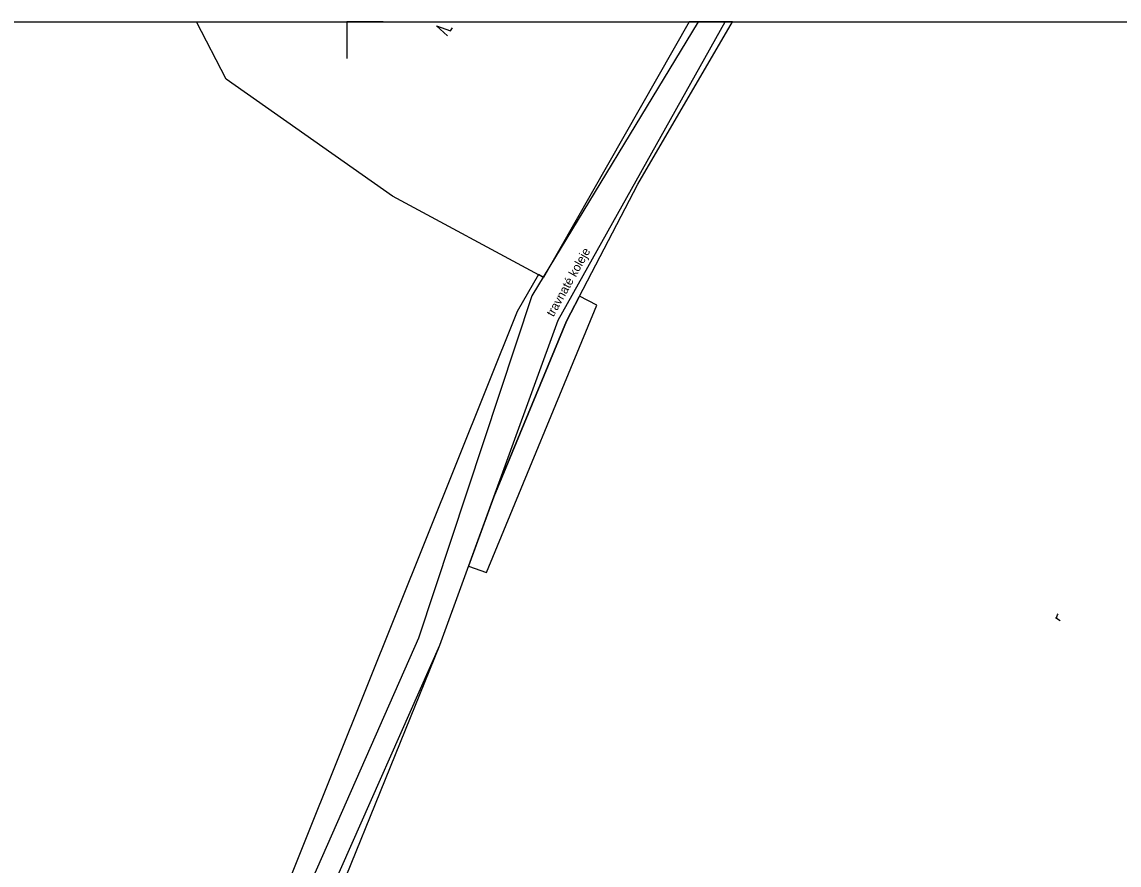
# Model space of a CAD drawing. Extents: x -636600 to -628587, y -1090963 to -1085869.
# Drawn here: x -629681.7 to -629531.6, y -1090043.3 to -1089927.9 of the extents above; entities that cross this region are included whole.
import ezdxf

# ---------------------------------------------------------------- set-up
doc = ezdxf.new("R2010")
doc.units = 0
for name, color, linetype in [('01_PARCELY_NÁVRH_PC', 7, 'Continuous'), ('08_LEGENDA_HV', 7, 'Continuous'), ('15', 7, 'Continuous'), ('40', 7, 'Continuous'), ('42', 7, 'Continuous'), ('43', 7, 'Continuous')]:
    doc.layers.add(name, color=color, linetype=linetype)

msp = doc.modelspace()

# ---------------------------------------------------------------- linework, layer by layer
at = {"layer": '01_PARCELY_NÁVRH_PC'}
msp.add_line((-629584.51, -1089927.9), (-629590.44, -1089927.9), dxfattribs=at)
for points in [[(-629590.44, -1089927.9), (-629610.34, -1089962.86), (-629611.05, -1089962.47), (-629613.94, -1089967.55), (-629651.31, -1090060.76), (-629656.7, -1090071.62), (-629663.92, -1090084.26), (-629669.51, -1090092.1), (-629671.7, -1090096.43), (-629679.1, -1090105.56), (-629740.1, -1090168.89), (-629745.82, -1090175.94), (-629753.08, -1090187.33), (-629759.69, -1090209.29), (-629763.83, -1090224.9)], [(-629757.08, -1090224.9), (-629756.4, -1090222.95), (-629754.36, -1090212.07), (-629743.98, -1090191.89), (-629738.43, -1090182.38), (-629727.31, -1090166.03), (-629671.82, -1090106.56), (-629662.5, -1090094.94), (-629652.06, -1090078.29), (-629645.47, -1090064.84), (-629624.55, -1090013.22), (-629617.14, -1089992.88), (-629607.22, -1089968.87), (-629597.44, -1089950.1), (-629584.51, -1089927.9)]]:
    msp.add_lwpolyline(points, dxfattribs=at)
msp.add_lwpolyline([(-629620.6, -1090002.37), (-629618.16, -1090003.26), (-629603.06, -1089966.65), (-629605.42, -1089965.42), (-629607.22, -1089968.87), (-629617.14, -1089992.88)], close=True, dxfattribs=at)
at = {"layer": '08_LEGENDA_HV'}
msp.add_line((-629847.27, -1089927.9), (-629007.27, -1089927.9), dxfattribs=at)
msp.add_lwpolyline([(-629632.27, -1089927.9), (-629637.27, -1089927.9), (-629637.27, -1089932.9)], dxfattribs=at)
at = {"layer": '40'}
for p, q in [((-629589.17, -1089927.9), (-629611.96, -1089965.4)), ((-629608.33, -1089968.7), (-629585.49, -1089927.9)), ((-629611.96, -1089965.4), (-629627.46, -1090012.25)), ((-629624.55, -1090013.22), (-629608.33, -1089968.7)), ((-629627.46, -1090012.25), (-629654.76, -1090074.11)), ((-629651.52, -1090074.2), (-629624.55, -1090013.22))]:
    msp.add_line(p, q, dxfattribs=at)
at = {"layer": '42'}
for p, q in [((-629653.77, -1089935.71), (-629657.83, -1089927.9)), ((-629590.44, -1089927.9), (-629610.34, -1089962.86)), ((-629631.02, -1089951.75), (-629653.77, -1089935.71)), ((-629610.34, -1089962.86), (-629631.02, -1089951.75))]:
    msp.add_line(p, q, dxfattribs=at)
at = {"layer": '43'}
for p, q in [((-629623.5, -1089929.81), (-629624.98, -1089928.41)), ((-629624.98, -1089928.41), (-629623.08, -1089929.13)), ((-629623.08, -1089929.13), (-629622.81, -1089928.71))]:
    msp.add_line(p, q, dxfattribs=at)
for points in [[(-629540.1, -1090009.58), (-629540.12, -1090009.45), (-629540.12, -1090009.33), (-629540.08, -1090009.17), (-629540.02, -1090009.03), (-629539.94, -1090008.89)], [(-629539.68, -1090009.85), (-629540.3, -1090009.46)]]:
    msp.add_lwpolyline(points, dxfattribs=at)

# ---------------------------------------------------------------- texts
at = {"layer": '15'}
msp.add_text('travnaté koleje', height=1.2, rotation=60.7648, dxfattribs=at).set_placement((-629608.99, -1089968.34))

doc.saveas('drawing.dxf')
